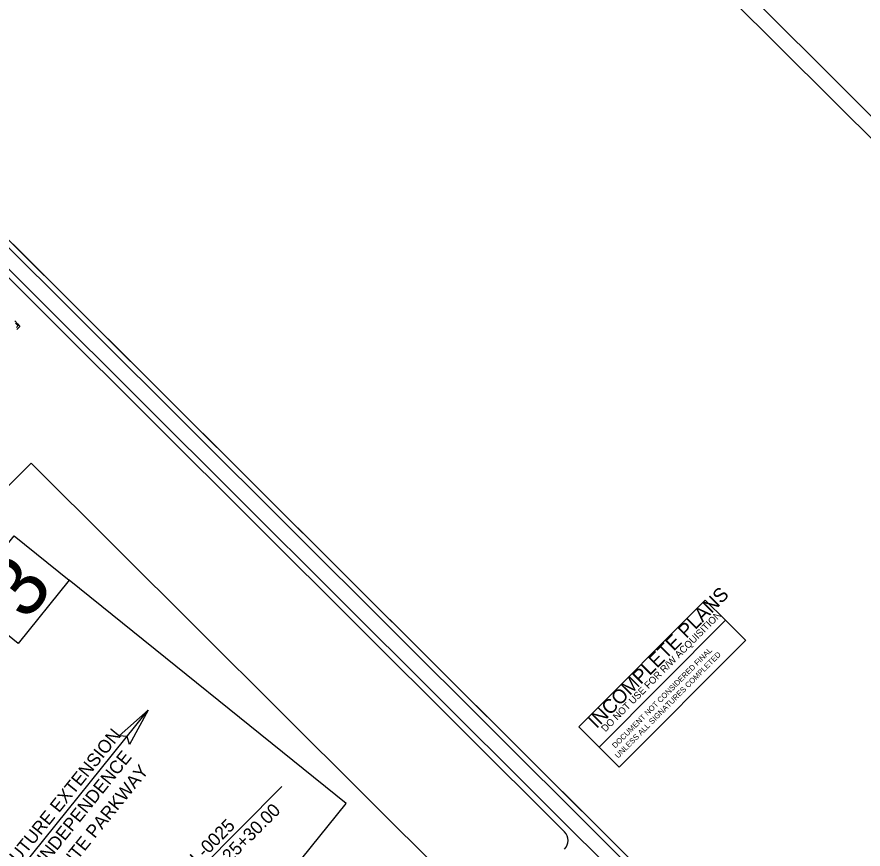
# Model space of a CAD drawing. Extents: x 1484850 to 1495577, y 495475 to 506245.
# Drawn here: x 1488945 to 1491030, y 499545 to 501594 of the extents above; entities that cross this region are included whole.
import ezdxf

# ---------------------------------------------------------------- set-up
doc = ezdxf.new("R2010")
doc.units = 0
for name, color, linetype in [('Cell Prop Down Guy _B', 7, 'Continuous'), ('Default', 7, 'Continuous'), ('Exist Utilities Sanitary Sewer Manhole CELL', 7, 'Continuous'), ('Exist Utilities Telephone UG Cable SUE LOS C', 7, 'Continuous'), ('Exist Utilities Telephone UG FO SUE LOS C', 7, 'Continuous'), ('Exist Utilities Water Meter CELL', 7, 'Continuous'), ('Exist Utilities Water UG Line SUE LOS B', 7, 'Continuous'), ('P Pole (Pow Co) CELL', 7, 'Continuous'), ('Prop Conduit _B', 7, 'Continuous'), ('Prop Directional Drill Conduit _B', 7, 'Continuous'), ('Prop Guy Wire', 7, 'Continuous'), ('Prop UG Pow Cables', 7, 'Continuous')]:
    doc.layers.add(name, color=color, linetype=linetype)

msp = doc.modelspace()

# ---------------------------------------------------------------- linework, layer by layer
at = {"layer": 'Cell Prop Down Guy _B'}
msp.add_line((1489673.9, 502665.1), (1492012.1, 500336.5), dxfattribs=at)
msp.add_lwpolyline([(1485019.4, 497803.9), (1488584.2, 501383.6), (1490922.5, 499055), (1487357.7, 495475.3)], close=True, dxfattribs=at)
at = {"layer": 'Default'}
for points in [[(1488940.2, 500845.4), (1488946.5, 500838.2), (1488951.4, 500832.2), (1488951.6, 500830.5), (1488951, 500829.6), (1488949.9, 500829.3), (1488946.4, 500824.7), (1488945.4, 500823.6)], [(1488944.7, 500829), (1488946.3, 500831), (1488947.4, 500833.6), (1488945.9, 500835.6), (1488941.9, 500840)]]:
    msp.add_lwpolyline(points, dxfattribs=at)
at = {"layer": 'Exist Utilities Sanitary Sewer Manhole CELL'}
msp.add_lwpolyline([(1489197, 499823.3), (1489269, 499886.6), (1489222.5, 499802.1), (1489217, 499822)], close=True, dxfattribs=at)
at = {"layer": 'Exist Utilities Telephone UG Cable SUE LOS C'}
msp.add_lwpolyline([(1486945.7, 498451.8), (1488980.9, 500495.4), (1490008.1, 499472.4), (1487973, 497428.8)], close=True, dxfattribs=at)
msp.add_lwpolyline([(1486945.7, 498451.8), (1488980.9, 500495.4), (1490008.1, 499472.4), (1487973, 497428.8)], close=True, dxfattribs=at)
at = {"layer": 'Exist Utilities Telephone UG FO SUE LOS C'}
msp.add_lwpolyline([(1488813.3, 500160.1), (1488938.9, 500315.8), (1489073.9, 500206.9)], dxfattribs=at)
msp.add_lwpolyline([(1488948.4, 500051.2), (1488813.3, 500160.1), (1488087.8, 499260.5), (1488879.1, 498569.1), (1489756.2, 499656.7), (1489073.9, 500206.9)], close=True, dxfattribs=at)
at = {"layer": 'Exist Utilities Water Meter CELL'}
msp.add_line((1488926.4, 499461.8), (1489269, 499886.6), dxfattribs=at)
at = {"layer": 'Exist Utilities Water UG Line SUE LOS B'}
msp.add_line((1489598, 499698.5), (1489242.3, 499341.4), dxfattribs=at)
at = {"layer": 'P Pole (Pow Co) CELL'}
msp.add_lwpolyline([(1488481.3, 501486.1), (1484916.4, 497906.4), (1487254.7, 495577.9), (1490819.6, 499157.6)], close=True, dxfattribs=at)
at = {"layer": 'Prop Conduit _B'}
msp.add_lwpolyline([(1490379.4, 499795.8), (1490329.4, 499845.6), (1490640.6, 500158), (1490690.6, 500108.3)], close=True, dxfattribs=at)
at = {"layer": 'Prop Directional Drill Conduit _B'}
for p, q in [((1490379.4, 499795.8), (1490690.6, 500108.3)), ((1490690.6, 500108.3), (1490740.6, 500058.5)), ((1490740.5, 500058.6), (1490429.3, 499746.1)), ((1490429.3, 499746.1), (1490379.4, 499795.8))]:
    msp.add_line(p, q, dxfattribs=at)
at = {"layer": 'Prop Guy Wire'}
for points in [[(1491992, 500411.6), (1495519.8, 503954.1), (1493277, 506187.7), (1489749.1, 502645.2)], [(1487337.5, 495550.5), (1490865.3, 499093), (1488622.4, 501326.5), (1485094.6, 497784)]]:
    msp.add_lwpolyline(points, close=True, dxfattribs=at)
at = {"layer": 'Prop UG Pow Cables'}
for points in [[(1490709.2, 499195.5), (1488519.7, 501375.9)], [(1490294.7, 499587.1), (1488519.7, 501354.7)]]:
    msp.add_lwpolyline(points, dxfattribs=at)
msp.add_arc((1490273.4, 499566), 30, 315.1191, 45.1191, dxfattribs=at)

# ---------------------------------------------------------------- texts
at = {"layer": 'Exist Utilities Water Meter CELL'}
for s, height, rotation, p in [('3', 150, 51.1156, (1488968.4, 500102.7)), ('FUTURE EXTENSION', 32, 51.1158, (1488932.5, 499488.1)), ('TO INDEPENDENCE', 32, 51.1158, (1488971.8, 499450.4)), ('POINTE PARKWAY', 32, 51.1158, (1489029.7, 499435.9)), ('-L- POT STA. 25+30.00', 32, 45.1191, (1489279, 499318.1)), ('END TIP HL-0025', 32, 45.1191, (1489241.6, 499355.3))]:
    msp.add_text(s, height=height, rotation=rotation, dxfattribs=at).set_placement(p)
at = {"layer": 'Prop Conduit _B'}
for s, height, p in [('INCOMPLETE PLANS', 34.56, (1490373.5, 499839.6)), ('DO NOT USE FOR R/W ACQUISITION', 17.28, (1490395.1, 499831.8))]:
    msp.add_text(s, height=height, rotation=45.1191, dxfattribs=at).set_placement(p)
at = {"layer": 'Prop Directional Drill Conduit _B'}
for s, p in [('DOCUMENT NOT CONSIDERED FINAL', (1490419.5, 499792.1)), ('UNLESS ALL SIGNATURES COMPLETED', (1490426.6, 499767.2))]:
    msp.add_text(s, height=13.5, rotation=45.1191, dxfattribs=at).set_placement(p)

doc.saveas('drawing.dxf')
